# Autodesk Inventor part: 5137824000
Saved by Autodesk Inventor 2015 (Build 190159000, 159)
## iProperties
Created: 2020-07
Part Number: 5137824000
Checked By: TraceParts S.A.
Material: Generic
Catalog Web Link: www.traceparts.com
Document SubType Name: Modeling
Designer: TraceParts
Density: 1 g/cm^3
Appearance: Default
Company: TraceParts S.A.
Author: TraceParts
REFERENCE: 5137824000
DESIGN: CVAT/4-4000/400 N D PTC 0,37KW (230/400V) 50HZ - 5137824000
SUPPLIER: Soler & Palau
TraceParts.PartNumber: 10-14122018-105188
TraceParts.PartTitle: CVAT-N
TraceParts.InstanceId: 10-14122018-1051886Y6WN9HA01IKBTH4480SAXUOY
TraceParts.PartStatus: Published
TraceParts.PartVersion: 1.0.4
TRACEPARTS: TRACEPARTS
TraceParts.PartLanguage: en
TraceParts.ClassPath: SOLER_PALAU:10-14122018-105188
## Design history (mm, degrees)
feature "5137824000"
body "Solid1"
